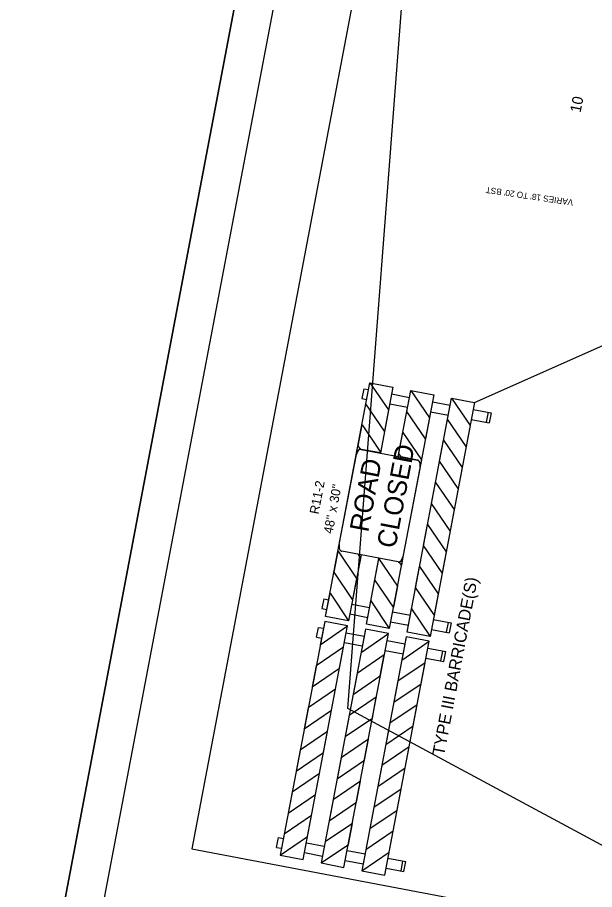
# Model space of a CAD drawing. Extents: x 1615642 to 1617075, y 899305 to 901510.
# Drawn here: x 1615680 to 1616055, y 899679 to 900246 of the extents above; entities that cross this region are included whole.
import ezdxf

# ---------------------------------------------------------------- set-up
doc = ezdxf.new("R2010")
doc.units = 0
for name, color, linetype in [('Default', 7, 'Continuous'), ('DEV BORDER CELL', 7, 'Continuous'), ('DEV TYPE 3 BARRICADE DOUBLE WITH R11-2 CELL', 7, 'Continuous'), ('Prop DSN Text', 7, 'Continuous'), ('Prop Horizontal Alignment Tick Label', 7, 'Continuous'), ('Scratch_Level_0', 7, 'Continuous'), ('Sheet Clip Boundary CELL', 7, 'Continuous'), ('Sheet Plot Border Outside CELL', 7, 'Continuous')]:
    doc.layers.add(name, color=color, linetype=linetype)

msp = doc.modelspace()

# ---------------------------------------------------------------- linework, layer by layer
at = {"layer": 'DEV BORDER CELL'}
msp.add_lwpolyline([(1616014.55, 901139.21), (1615734.74, 899665.53), (1616766.32, 899469.67), (1617046.12, 900943.35)], close=True, dxfattribs=at)
at = {"layer": 'DEV TYPE 3 BARRICADE DOUBLE WITH R11-2 CELL'}
for p, q in [((1615880.11, 899856.44), (1615908.98, 900008.47)), ((1615906.38, 899994.79), (1615908.98, 900008.47)), ((1615908.98, 900008.47), (1615923.89, 900005.64)), ((1615908.98, 900008.47), (1615921.06, 899990.73)), ((1615904.9, 900004.56), (1615903.67, 899998.11)), ((1615904.9, 900004.56), (1615908.12, 900003.95)), ((1615923.89, 900005.64), (1615915.75, 899962.77)), ((1615927.36, 899960.56), (1615935.5, 900003.43)), ((1615932.9, 899989.75), (1615935.5, 900003.43)), ((1615935.5, 900003.43), (1615950.41, 900000.6)), ((1615935.5, 900003.43), (1615947.58, 899985.7)), ((1615903.67, 899998.11), (1615906.9, 899997.5)), ((1615950.41, 900000.6), (1615921.54, 899848.58)), ((1615923.03, 900001.12), (1615934.64, 899998.92)), ((1615933.16, 899846.37), (1615962.02, 899998.4)), ((1615949.55, 899996.09), (1615961.16, 899993.88)), ((1615959.42, 899984.72), (1615962.02, 899998.4)), ((1615962.02, 899998.4), (1615974.1, 899980.66)), ((1615962.02, 899998.4), (1615976.93, 899995.57)), ((1615918.46, 899977.05), (1615906.38, 899994.79)), ((1615921.06, 899990.73), (1615918.46, 899977.05)), ((1615921.8, 899994.67), (1615933.42, 899992.46)), ((1615976.93, 899995.57), (1615948.06, 899843.54)), ((1615976.07, 899991.05), (1615987.68, 899988.85)), ((1615944.98, 899972.02), (1615932.9, 899989.75)), ((1615947.58, 899985.7), (1615944.98, 899972.02)), ((1615948.32, 899989.63), (1615959.94, 899987.43)), ((1615971.5, 899966.98), (1615959.42, 899984.72)), ((1615974.84, 899984.6), (1615986.46, 899982.39)), ((1615985.75, 899989.21), (1615984.52, 899982.76)), ((1615987.68, 899988.85), (1615986.46, 899982.39)), ((1615901.19, 899967.43), (1615903.79, 899981.11)), ((1615903.79, 899981.11), (1615915.86, 899963.37)), ((1615974.1, 899980.66), (1615971.5, 899966.98)), ((1615927.71, 899962.39), (1615930.31, 899976.07)), ((1615930.31, 899976.07), (1615942.38, 899958.34)), ((1615902.74, 899965.15), (1615901.19, 899967.43)), ((1615954.23, 899957.36), (1615956.83, 899971.04)), ((1615956.83, 899971.04), (1615968.9, 899953.3)), ((1615915.75, 899962.77), (1615903.26, 899965.14)), ((1615915.86, 899963.37), (1615915.75, 899962.77)), ((1615929.19, 899960.21), (1615927.71, 899962.39)), ((1615939.85, 899958.19), (1615929.19, 899960.21)), ((1615942.38, 899958.34), (1615941.54, 899953.89)), ((1615966.3, 899939.62), (1615954.23, 899957.36)), ((1615941.53, 899953.86), (1615930.42, 899895.32)), ((1615968.9, 899953.3), (1615966.3, 899939.62)), ((1615949.03, 899930), (1615951.63, 899943.68)), ((1615951.63, 899943.68), (1615963.71, 899925.94)), ((1615961.11, 899912.26), (1615949.03, 899930)), ((1615963.71, 899925.94), (1615961.11, 899912.26)), ((1615943.83, 899902.58), (1615946.42, 899916.26)), ((1615946.42, 899916.26), (1615958.5, 899898.52)), ((1615955.9, 899884.84), (1615943.83, 899902.58)), ((1615885.59, 899885.29), (1615888.19, 899898.97)), ((1615888.19, 899898.97), (1615900.26, 899881.23)), ((1615903.16, 899896.48), (1615895.02, 899853.61)), ((1615902.86, 899894.91), (1615901.59, 899896.78)), ((1615901.59, 899896.78), (1615903.16, 899896.48)), ((1615903.16, 899896.48), (1615902.86, 899894.91)), ((1615906.64, 899851.41), (1615914.78, 899894.28)), ((1615912.11, 899880.25), (1615914.71, 899893.93)), ((1615914.71, 899893.93), (1615926.79, 899876.2)), ((1615930.42, 899895.31), (1615929.38, 899889.87)), ((1615958.5, 899898.52), (1615955.9, 899884.84)), ((1615929.38, 899889.87), (1615927.98, 899891.94)), ((1615938.63, 899875.22), (1615941.23, 899888.9)), ((1615941.23, 899888.9), (1615953.31, 899871.16)), ((1615897.67, 899867.55), (1615885.59, 899885.29)), ((1615900.26, 899881.23), (1615897.67, 899867.55)), ((1615924.19, 899862.52), (1615912.11, 899880.25)), ((1615880.11, 899856.44), (1615882.99, 899871.61)), ((1615882.99, 899871.61), (1615895.02, 899853.61)), ((1615926.79, 899876.2), (1615924.19, 899862.52)), ((1615950.71, 899857.48), (1615938.63, 899875.22)), ((1615953.31, 899871.16), (1615950.71, 899857.48)), ((1615878.97, 899868.03), (1615877.75, 899861.57)), ((1615878.97, 899868.03), (1615882.2, 899867.41)), ((1615906.64, 899851.41), (1615909.51, 899866.57)), ((1615909.51, 899866.57), (1615921.54, 899848.58)), ((1615877.75, 899861.57), (1615880.97, 899860.96)), ((1615897.1, 899864.58), (1615908.72, 899862.38)), ((1615933.16, 899846.37), (1615936.04, 899861.54)), ((1615936.04, 899861.54), (1615948.06, 899843.54)), ((1615895.02, 899853.61), (1615880.11, 899856.44)), ((1615895.02, 899853.61), (1615880.11, 899856.44)), ((1615895.88, 899858.13), (1615907.49, 899855.92)), ((1615923.62, 899859.55), (1615935.24, 899857.34)), ((1615950.14, 899854.51), (1615961.76, 899852.31)), ((1615879.52, 899853.3), (1615850.65, 899701.27)), ((1615865.56, 899698.44), (1615894.42, 899850.47)), ((1615874.21, 899842.94), (1615875.43, 899849.4)), ((1615875.43, 899849.4), (1615878.66, 899848.78)), ((1615879.52, 899853.3), (1615876.64, 899838.14)), ((1615876.64, 899838.14), (1615894.42, 899850.47)), ((1615906.04, 899848.26), (1615877.17, 899696.24)), ((1615894.42, 899850.47), (1615879.52, 899853.3)), ((1615894.42, 899850.47), (1615879.52, 899853.3)), ((1615906.04, 899848.26), (1615903.16, 899833.1)), ((1615920.94, 899845.43), (1615906.04, 899848.26)), ((1615920.94, 899845.43), (1615906.04, 899848.26)), ((1615921.54, 899848.58), (1615906.64, 899851.41)), ((1615921.54, 899848.58), (1615906.64, 899851.41)), ((1615922.4, 899853.09), (1615934.01, 899850.89)), ((1615959.82, 899852.67), (1615958.6, 899846.22)), ((1615961.76, 899852.31), (1615960.53, 899845.85)), ((1615874.21, 899842.94), (1615877.44, 899842.33)), ((1615892.08, 899693.41), (1615920.94, 899845.43)), ((1615893.57, 899845.95), (1615905.18, 899843.75)), ((1615903.16, 899833.1), (1615920.94, 899845.43)), ((1615932.56, 899843.23), (1615903.69, 899691.2)), ((1615932.56, 899843.23), (1615929.68, 899828.07)), ((1615947.47, 899840.4), (1615932.56, 899843.23)), ((1615947.47, 899840.4), (1615932.56, 899843.23)), ((1615948.06, 899843.54), (1615933.16, 899846.37)), ((1615948.06, 899843.54), (1615933.16, 899846.37)), ((1615948.92, 899848.06), (1615960.53, 899845.85)), ((1615892.34, 899839.5), (1615903.96, 899837.3)), ((1615918.6, 899688.37), (1615947.47, 899840.4)), ((1615920.09, 899840.92), (1615931.7, 899838.71)), ((1615929.68, 899828.07), (1615947.47, 899840.4)), ((1615891.78, 899836.53), (1615874.04, 899824.46)), ((1615889.18, 899822.85), (1615891.78, 899836.53)), ((1615918.3, 899831.5), (1615900.56, 899819.42)), ((1615915.7, 899817.82), (1615918.3, 899831.5)), ((1615918.86, 899834.47), (1615930.48, 899832.26)), ((1615946.61, 899835.88), (1615958.22, 899833.68)), ((1615955.06, 899827.59), (1615956.29, 899834.04)), ((1615957, 899827.22), (1615958.22, 899833.68)), ((1615944.82, 899826.46), (1615927.08, 899814.39)), ((1615942.22, 899812.78), (1615944.82, 899826.46)), ((1615945.38, 899829.43), (1615957, 899827.22)), ((1615874.04, 899824.46), (1615871.44, 899810.78)), ((1615871.44, 899810.78), (1615889.18, 899822.85)), ((1615900.56, 899819.42), (1615897.97, 899805.74)), ((1615897.97, 899805.74), (1615915.7, 899817.82)), ((1615927.08, 899814.39), (1615924.49, 899800.71)), ((1615886.58, 899809.17), (1615868.85, 899797.1)), ((1615883.99, 899795.49), (1615886.58, 899809.17)), ((1615924.49, 899800.71), (1615942.22, 899812.78)), ((1615913.1, 899804.14), (1615895.37, 899792.06)), ((1615910.51, 899790.46), (1615913.1, 899804.14)), ((1615939.62, 899799.1), (1615921.89, 899787.03)), ((1615937.03, 899785.42), (1615939.62, 899799.1)), ((1615868.85, 899797.1), (1615866.25, 899783.42)), ((1615866.25, 899783.42), (1615883.99, 899795.49)), ((1615895.37, 899792.06), (1615892.77, 899778.38)), ((1615892.77, 899778.38), (1615910.51, 899790.46)), ((1615921.89, 899787.03), (1615919.29, 899773.35)), ((1615881.38, 899781.75), (1615863.64, 899769.67)), ((1615878.78, 899768.07), (1615881.38, 899781.75)), ((1615919.29, 899773.35), (1615937.03, 899785.42)), ((1615907.9, 899776.71), (1615890.16, 899764.64)), ((1615905.3, 899763.03), (1615907.9, 899776.71)), ((1615863.64, 899769.67), (1615861.04, 899755.99)), ((1615934.42, 899771.68), (1615916.68, 899759.6)), ((1615931.82, 899758), (1615934.42, 899771.68)), ((1615861.04, 899755.99), (1615878.78, 899768.07)), ((1615890.16, 899764.64), (1615887.56, 899750.96)), ((1615887.56, 899750.96), (1615905.3, 899763.03)), ((1615916.68, 899759.6), (1615914.08, 899745.92)), ((1615914.08, 899745.92), (1615931.82, 899758)), ((1615876.18, 899754.39), (1615858.45, 899742.31)), ((1615873.58, 899740.71), (1615876.18, 899754.39)), ((1615902.7, 899749.35), (1615884.97, 899737.28)), ((1615900.1, 899735.67), (1615902.7, 899749.35)), ((1615858.45, 899742.31), (1615855.85, 899728.63)), ((1615855.85, 899728.63), (1615873.58, 899740.71)), ((1615929.22, 899744.32), (1615911.49, 899732.24)), ((1615926.63, 899730.64), (1615929.22, 899744.32)), ((1615884.97, 899737.28), (1615882.37, 899723.6)), ((1615882.37, 899723.6), (1615900.1, 899735.67)), ((1615911.49, 899732.24), (1615908.89, 899718.56)), ((1615908.89, 899718.56), (1615926.63, 899730.64)), ((1615870.99, 899727.03), (1615853.25, 899714.95)), ((1615868.39, 899713.35), (1615870.99, 899727.03)), ((1615897.51, 899721.99), (1615879.77, 899709.92)), ((1615894.91, 899708.31), (1615897.51, 899721.99)), ((1615848.28, 899706.4), (1615849.51, 899712.86)), ((1615849.51, 899712.86), (1615852.74, 899712.24)), ((1615853.25, 899714.95), (1615850.65, 899701.27)), ((1615850.65, 899701.27), (1615868.39, 899713.35)), ((1615924.03, 899716.96), (1615906.29, 899704.88)), ((1615921.43, 899703.28), (1615924.03, 899716.96)), ((1615867.64, 899709.41), (1615879.26, 899707.21)), ((1615879.77, 899709.92), (1615877.17, 899696.24)), ((1615877.17, 899696.24), (1615894.91, 899708.31)), ((1615848.28, 899706.4), (1615851.51, 899705.79)), ((1615850.65, 899701.27), (1615865.56, 899698.44)), ((1615866.42, 899702.96), (1615878.03, 899700.76)), ((1615894.16, 899704.38), (1615905.78, 899702.17)), ((1615906.29, 899704.88), (1615903.69, 899691.2)), ((1615903.69, 899691.2), (1615921.43, 899703.28)), ((1615877.17, 899696.24), (1615892.08, 899693.41)), ((1615892.94, 899697.93), (1615904.55, 899695.72)), ((1615920.68, 899699.34), (1615932.3, 899697.14)), ((1615929.14, 899691.05), (1615930.36, 899697.51)), ((1615931.07, 899690.68), (1615932.3, 899697.14)), ((1615903.69, 899691.2), (1615918.6, 899688.37)), ((1615919.46, 899692.89), (1615931.07, 899690.68))]:
    msp.add_line(p, q, dxfattribs=at)
for points in [[(1615888.99, 899903.18), (1615900.11, 899961.73)], [(1615903.26, 899965.14), (1615939.85, 899958.19)], [(1615927.26, 899891.91), (1615890.67, 899898.86)]]:
    msp.add_lwpolyline(points, dxfattribs=at)
for centre, major_axis, start_param, end_param in [((1615902.52, 899961.27), (0.73, 3.87), 0, 1.570796), ((1615902.52, 899961.27), (0.73, 3.87), 6.283185, 6.491582), ((1615939.12, 899954.32), (-0.73, -3.87), 1.570796, 3.141593), ((1615939.12, 899954.32), (0.73, 3.87), 4.712389, 6.283185), ((1615891.41, 899902.72), (-0.73, -3.87), 4.712162, 6.283185), ((1615928, 899895.77), (-0.73, -3.87), 0, 1.571024), ((1615928, 899895.77), (-0.73, -3.87), 0.287132, 1.570688)]:
    msp.add_ellipse(centre, major_axis=major_axis, ratio=0.625, start_param=start_param, end_param=end_param, dxfattribs=at)
at = {"layer": 'Prop DSN Text'}
msp.add_line((1615976.93, 899995.57), (1616172.86, 900082.64), dxfattribs=at)
at = {"layer": 'Scratch_Level_0'}
msp.add_lwpolyline([(1616054.34, 901080.76), (1615793.19, 899705.33), (1616726.52, 899528.12), (1616890.46, 900391.55), (1616774.26, 900413.61), (1616871.48, 900925.61)], close=True, dxfattribs=at)
at = {"layer": 'Sheet Clip Boundary CELL'}
msp.add_lwpolyline([(1616176.29, 901060.7), (1616913.78, 900900.04), (1616896.28, 900812.91), (1616872.94, 900688.21), (1616835.87, 900695.21), (1616753.94, 900262.18), (1616898.09, 900233.43), (1616663.91, 899565.73), (1616252.62, 899604.04), (1615894.68, 899796.73), (1615981.58, 900932.46), (1616145.94, 900899.57)], close=True, dxfattribs=at)
at = {"layer": 'Sheet Plot Border Outside CELL'}
for points in [[(1616760.47, 899304.87), (1615679.78, 899510.06), (1615994.65, 901168.43), (1617075.34, 900963.24)], [(1616760.47, 899304.87), (1617075.34, 900963.24), (1615994.65, 901168.43), (1615679.78, 899510.06)]]:
    msp.add_lwpolyline(points, close=True, dxfattribs=at)

# ---------------------------------------------------------------- texts
at = {"layer": 'Default'}
msp.add_text("VARIES 18' TO 20' BST", height=4, rotation=171.6581, dxfattribs=at).set_placement((1616041.32, 900127.5))
at = {"layer": 'DEV TYPE 3 BARRICADE DOUBLE WITH R11-2 CELL'}
for s, height, p in [('CLOSED', 12.369, (1615925.46, 899900.27)), ('ROAD', 12.369, (1615907.8, 899910.8)), ('R11-2', 6, (1615875.53, 899922.64)), ("48'' x 30''", 6, (1615884.58, 899909.94)), ('TYPE III BARRICADE(S)', 7.8816, (1615957.15, 899765.64))]:
    msp.add_text(s, height=height, rotation=79.2494, dxfattribs=at).set_placement(p)
at = {"layer": 'Prop Horizontal Alignment Tick Label'}
msp.add_text('10', height=7, rotation=78.8364, dxfattribs=at).set_placement((1616045.82, 900183.62))

doc.saveas('drawing.dxf')
